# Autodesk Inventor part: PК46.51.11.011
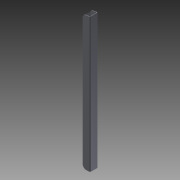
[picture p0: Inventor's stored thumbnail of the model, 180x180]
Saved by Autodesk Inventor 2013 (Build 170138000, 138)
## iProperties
Shininess: 64.0
Length Units: 11269
Angle Units: 11279
Time Units: 11290
Mass Units: 11283
Length Display Precision: 3
Angle Display Precision: 2
Compacted: True
Part Number: PК46.51.11.011
Document SubType Name: Modeling
Created: 2004-07
Material: Steel, Mild
Designer: =<Author>
Manufacturer: Standard
Standards Organization: Custom
Description: pipe
Density: 7.86 g/cm^3
Mass: 850.491 g
Surface Area: 1087.08 cm^2
Volume: 108.205 cm^3
Density: 0.0
Volumn: 0.0
Area: 0.0
PropertySet Name: Model Information
Control State: 0
Master: False
Checked Out: False
Checked Out Date: 2008-10-15
Last Check In Date: 2008-10-15
Author: PVitaliy
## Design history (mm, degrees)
sketch "Эскиз1"
  geometry: L1 (4, 0)-(26, 0); L2 (30, 4)-(30, 26); L3 (26, 30)-(4, 30); L4 (0, 26)-(0, 4); L5 (2, 26)-(2, 4); L6 (4, 2)-(26, 2); L7 (28, 4)-(28, 26); L8 (26, 28)-(4, 28); A1 r 4 centre (4, 26) between (4, 30) and (0, 26); A2 r 4 centre (26, 26) between (30, 26) and (26, 30); A3 r 4 centre (26, 4) between (26, 0) and (30, 4); A4 r 4 centre (4, 4) between (0, 4) and (4, 0); A5 r 2 centre (4, 26) between (4, 28) and (2, 26); A6 r 2 centre (4, 4) between (2, 4) and (4, 2); A7 r 2 centre (26, 4) between (26, 2) and (28, 4); A8 r 2 centre (26, 26) between (28, 26) and (26, 28); 3 further points
  constraints: 16 end point, 16 point on circle, 8 centre point, 8 tangent, 6 point on line, 4 parallel, 2 equal radius, 2 perpendicular, 1 horizontal, 8 other
  dimensions: "d0" = 30 distance of point (0, 30) point (0, 0); "d1" = 30 distance of point (0, 0) point (30, 0); "d2" = 4 radius of A1; "d3" = 4 radius of A2; "d4" = 2 distance between parallel lines of L1 L6
extrude "Выдавливание1" new body sketch "Эскиз1" distance "d5" = 514; taper "d6" = 0 deg
sketch "Эскиз2"
  geometry: L1 (0, -514)-(22, -514) reference; L2 (-4, 0)-(-4, -514) reference; L3 (26, 0)-(26, -514) reference; L4 (26, -514)-(22, -514) reference; L5 (0, -514)-(-4, -514) reference; L6 (26, -514)-(-4, -508.71)
  constraints: 2 end point, 1 point on line
  dimensions: "d7" = 10 deg angle of L1 L6
extrude "Выдавливание2" cut sketch "Эскиз2" stored distance "d8" = 10; taper "d9" = 0 deg
sketch "Эскиз3"
  geometry: L1 (0, -509.415)-(22, -513.295) reference; L2 (0, -509.415)-(-4, -508.71) reference; L3 (-4, 0)-(-4, -508.71) reference; L4 (-4, -500.71)-(4, -510.121); L5 (22, 0)-(0, 0) reference; L6 (-4, 0)-(0, 0) reference; L7 (-4, -10)-(6, 0)
  constraints: 4 end point, 4 point on line
  dimensions: "d10" = 8 distance from line of L4.end L3; "d11" = 8 distance of L4.start L2.end; "d14" = 10 horizontal distance of L7.start L7.end; "d15" = 10 horizontal distance of L7.start L7.end
extrude "Выдавливание3" cut sketch "Эскиз3" stored distance "d12" = 10; taper "d13" = 0 deg
body "Solid1"
